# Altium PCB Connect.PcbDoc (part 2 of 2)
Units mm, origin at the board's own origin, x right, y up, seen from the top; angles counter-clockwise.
Board outline 480 x 50 mm, 2 copper layers (Top Layer, Bottom Layer); 349 components, 200 nets, 1147 pads, 734 vias.
Unrouted connection lines stored in the file: 1.
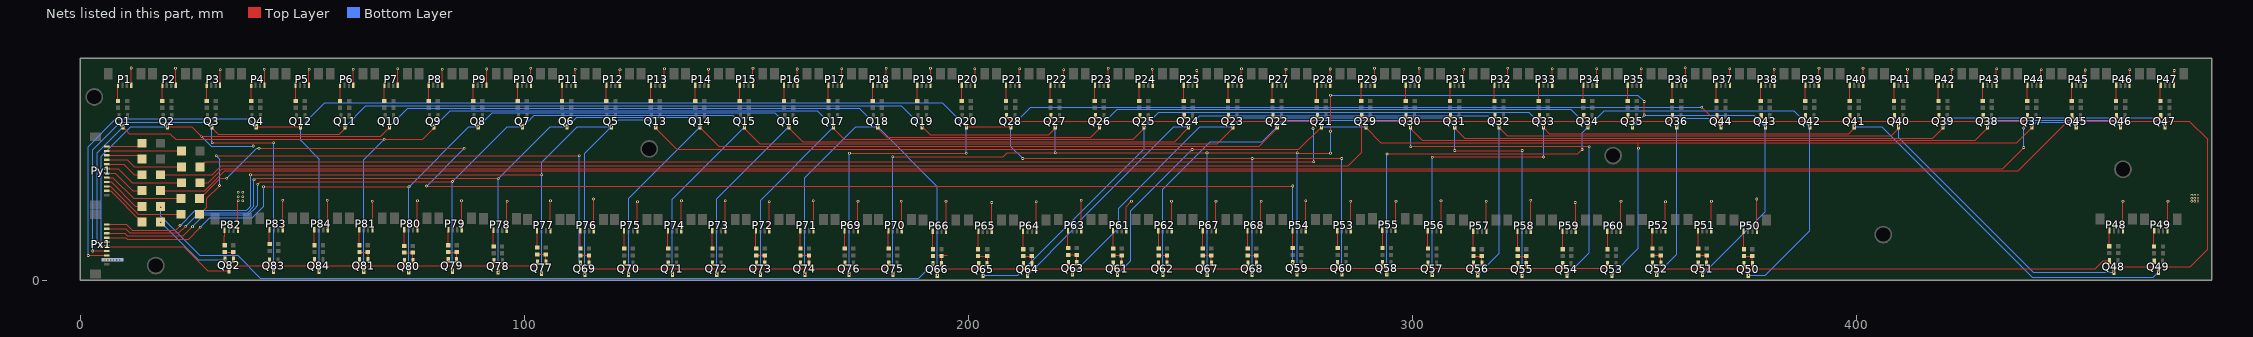
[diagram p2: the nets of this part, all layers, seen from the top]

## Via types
v1: diameter 1.27, hole 0.711, Top Layer to Bottom Layer, tented both sides, 396 vias
v2: diameter 0.6, hole 0.3, Top Layer to Bottom Layer, 231 vias
v3: diameter 0.5, hole 0.3, Top Layer to Bottom Layer, 107 vias

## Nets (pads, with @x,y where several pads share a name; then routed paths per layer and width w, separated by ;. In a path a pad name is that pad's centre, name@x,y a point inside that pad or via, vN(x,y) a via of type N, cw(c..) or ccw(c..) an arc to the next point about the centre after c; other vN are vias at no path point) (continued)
NetD4_1: D4.1 Q21.2 Q22.2 Q23.2 Q24.2 Q25.2 Q26.2 Q27.2 Q28.2 | length 339.4
  Top Layer w0.254: D4.1@26.992,25.527 28.135,26.67 v2(277.749,26.67) ; Q28.2@208.621,37.064 208.621,36.743 209.55,35.814 218.567,35.814 ; Q27.2@218.617,37.064 218.617,35.864 218.567,35.814 ; Q26.2@228.613,37.064 228.613,35.827 228.6,35.814 ; Q25.2@238.609,37.064 238.609,35.838 238.633,35.814 ; Q24.2@248.605,37.064 248.605,35.875 248.666,35.814 ; Q23.2@258.601,37.064 258.601,35.843 258.572,35.814 ; Q22.2@268.597,37.064 268.597,35.822 268.605,35.814 ; v2(277.622,34.163) 277.622,35.814 ; Q21.2@278.593,37.064 278.593,36.785 277.622,35.814 ; 218.567,35.814 228.6,35.814 ; 228.6,35.814 238.633,35.814 ; 238.633,35.814 248.666,35.814 ; 248.666,35.814 258.572,35.814 ; 258.572,35.814 268.605,35.814 ; 268.605,35.814 277.622,35.814
  Bottom Layer w0.254: v2(277.622,34.163) 277.749,34.036 v2(277.749,26.67)
NetD5_1: D5.1 Q29.2 Q30.2 Q31.2 Q32.2 Q33.2 Q34.2 Q35.2 Q36.2 | length 359.5
  Top Layer w0.254: D5.1@18.102,23.749 29.718,23.749 31.75,25.781 285.496,25.781 288.589,28.874 Q29.2@288.589,36.785 ; Q29.2@288.589,37.064 Q29.2@288.589,36.785 ; Q30.2@298.585,37.064 298.585,35.822 298.577,35.814 ; Q31.2@308.581,37.064 308.581,35.843 308.61,35.814 ; Q32.2@318.577,37.064 318.577,35.875 318.516,35.814 ; Q33.2@328.573,37.064 328.573,35.838 328.549,35.814 ; Q34.2@338.569,37.064 338.569,35.814 ; Q35.2@348.565,37.064 348.565,35.891 348.488,35.814 ; Q36.2@358.56,37.064 358.56,36.742 357.632,35.814 348.488,35.814 ; Q29.2@288.589,36.785 289.56,35.814 298.577,35.814 ; 298.577,35.814 308.61,35.814 ; 308.61,35.814 318.516,35.814 ; 318.516,35.814 328.549,35.814 ; 328.549,35.814 338.569,35.814 ; 338.569,35.814 348.488,35.814
NetD6_1: D6.1 Q37.2 Q38.2 Q39.2 Q40.2 Q41.2 Q42.2 Q43.2 Q44.2 | length 498.8
  Top Layer w0.254: D6.1@26.992,21.971 28.829,21.971 32.004,25.146 432.943,25.146 437.642,29.845 v2(437.642,29.909) ; Q44.2@368.556,37.064 368.556,36.828 369.57,35.814 378.587,35.814 ; Q43.2@378.552,37.064 378.552,35.849 378.587,35.814 ; Q42.2@388.548,37.064 388.548,35.886 388.62,35.814 ; Q41.2@398.544,37.064 398.544,35.832 398.526,35.814 ; Q40.2@408.54,37.064 408.54,35.833 408.559,35.814 ; Q39.2@418.536,37.064 418.536,35.885 418.465,35.814 ; Q38.2@428.532,37.064 428.532,35.848 428.498,35.814 ; v2(437.642,34.29) 437.642,35.814 ; Q37.2@438.528,37.064 438.528,36.7 437.642,35.814 ; 378.587,35.814 388.62,35.814 ; 388.62,35.814 398.526,35.814 ; 398.526,35.814 408.559,35.814 ; 408.559,35.814 418.465,35.814 ; 418.465,35.814 428.498,35.814 ; 428.498,35.814 437.642,35.814
  Bottom Layer w0.254: v2(437.642,29.909) v2(437.642,34.29)
NetD7_1: D7.1 Q45.2 Q46.2 Q47.2 Q48.2 Q49.2 Q50.2 Q51.2 Q52.2 | length 629.8
  Top Layer w0.254: D7.1@18.102,20.193 28.067,20.193 32.512,24.638 436.419,24.638 Q45.2@448.524,36.743 ; Q52.2@354.063,3.81 354.063,3.442 354.965,2.54 364.363,2.54 ; Q51.2@364.36,3.81 364.36,2.543 364.363,2.54 ; Q50.2@374.664,3.683 374.664,2.554 374.65,2.54 ; Q45.2@448.524,37.064 Q45.2@448.524,36.743 ; Q46.2@458.52,37.064 458.52,35.864 458.47,35.814 ; Q49.2@467.045,4.298 467.045,3.114 466.979,3.048 ; Q47.2@468.516,37.064 Q47.2@468.516,36.843 ; 364.363,2.54 374.65,2.54 ; 374.65,2.54 453.771,2.54 455.572,4.341 Q48.2@457.006,4.341 457.006,4.004 457.962,3.048 466.979,3.048 ; Q45.2@448.524,36.743 449.453,35.814 458.47,35.814 ; 458.47,35.814 467.487,35.814 Q47.2@468.516,36.843 ; 466.979,3.048 475.107,3.048 479.044,6.985 479.044,31.75 474.98,35.814 469.519,35.814 468.516,36.817 Q47.2@468.516,36.843
NetD8_1: D8.1 Q53.2 Q54.2 Q55.2 Q56.2 Q57.2 Q58.2 Q59.2 Q60.2 | length 367.8
  Top Layer w0.254: D8.1@26.865,18.415 27.712,19.262 27.855,19.262 31.579,22.987 v2(33.02,22.987) ; v2(40.259,29.718) v2(86.487,29.718) ; v2(77.978,21.209) v2(273.05,21.209) ; v2(273.057,3.937) 273.057,3.676 274.056,2.677 283.21,2.677 ; Q60.2@283.167,3.937 283.167,2.72 283.21,2.677 ; Q58.2@293.276,3.937 293.276,2.771 293.37,2.677 ; Q57.2@303.513,3.81 303.513,2.694 303.53,2.677 ; Q56.2@313.756,3.79 313.756,2.738 313.817,2.677 ; Q55.2@323.733,3.683 323.733,2.687 323.723,2.677 ; Q54.2@333.843,3.683 333.843,2.717 333.883,2.677 ; Q53.2@343.953,3.683 343.953,3.339 343.291,2.677 333.883,2.677 ; 283.21,2.677 293.37,2.677 ; 293.37,2.677 303.53,2.677 ; 303.53,2.677 313.817,2.677 ; 313.817,2.677 323.723,2.677 ; 323.723,2.677 333.883,2.677
  Bottom Layer w0.254: v2(33.02,22.987) 39.751,29.718 v2(40.259,29.718) ; v2(77.978,21.209) v2(86.487,29.718) ; v2(273.05,21.209) 273.057,21.202 v2(273.057,3.937)
NetD9_1: D9.1 Q61.2 Q62.2 Q63.2 Q64.2 Q65.2 Q66.2 Q67.2 Q68.2 | length 263.2
  Top Layer w0.254: v2(18.102,16.442) D9.1@18.102,16.637 ; v2(192.024,3.683) Q66.2@192.05,3.683 192.05,3.403 192.913,2.54 202.311,2.54 ; Q65.2@202.333,3.683 202.333,2.562 202.311,2.54 ; Q64.2@212.397,3.683 212.397,2.614 212.471,2.54 ; Q63.2@222.507,3.937 222.507,2.543 222.504,2.54 ; Q61.2@232.617,3.81 232.617,2.587 232.664,2.54 ; Q62.2@242.854,3.81 242.854,2.637 242.951,2.54 ; Q67.2@252.837,3.81 252.837,2.56 252.857,2.54 ; Q68.2@262.947,3.81 262.763,3.626 262.763,3.302 262.001,2.54 252.857,2.54 ; 202.311,2.54 212.471,2.54 ; 212.471,2.54 222.504,2.54 ; 222.504,2.54 232.664,2.54 ; 232.664,2.54 242.951,2.54 ; 242.951,2.54 252.857,2.54
  Bottom Layer w0.254: v2(18.102,16.442) 18.102,14.41 26.924,5.588 35.433,5.588 40.576,0.445 188.785,0.445 v2(192.024,3.683)
NetD10_1: D10.1 Q69.2 Q70.2 Q71.2 Q72.2 Q73.2 Q74.2 Q75.2 Q76.2 | length 200
  Top Layer w0.254: D10.1@26.865,14.859 28.448,16.442 28.448,18.415 v2(31.369,21.336) ; v2(30.607,28.067) v2(112.395,28.067) ; v2(112.695,3.81) 112.695,3.637 113.792,2.54 122.555,2.54 ; Q70.2@122.551,3.81 122.555,3.806 122.555,2.54 ; Q71.2@132.407,3.81 132.407,2.613 132.334,2.54 ; Q72.2@142.39,3.81 142.39,2.563 142.367,2.54 ; Q73.2@152.246,3.81 152.246,2.567 152.273,2.54 ; Q74.2@162.229,3.81 162.306,3.733 162.306,2.54 ; Q76.2@172.212,3.81 172.212,2.54 ; Q75.2@182.068,3.81 181.864,3.606 181.864,3.302 181.102,2.54 172.212,2.54 ; 122.555,2.54 132.334,2.54 ; 132.334,2.54 142.367,2.54 ; 142.367,2.54 152.273,2.54 ; 152.273,2.54 162.306,2.54 ; 162.306,2.54 172.212,2.54
  Bottom Layer w0.254: v2(30.607,28.067) 31.369,27.305 v2(31.369,21.336) ; v2(112.395,28.067) 112.395,4.11 v2(112.695,3.81)
NetD11_1: D11.1 Q77.2 Q78.2 Q79.2 Q80.2 Q81.2 Q82.2 Q83.2 Q84.2 | length 96.8
  Top Layer w0.254: Q82.2@32.578,4.379 33.655,3.302 42.545,3.302 ; Q83.2@42.611,4.532 42.611,3.368 42.545,3.302 ; Q84.2@52.798,4.572 52.798,3.336 52.832,3.302 ; Q81.2@62.908,4.572 62.908,3.386 62.992,3.302 ; Q80.2@73.018,4.445 73.018,3.309 73.025,3.302 ; Q79.2@82.873,4.572 82.873,3.371 82.804,3.302 ; Q78.2@93.157,4.405 93.157,3.302 ; Q77.2@102.966,4.064 102.966,3.779 102.489,3.302 93.157,3.302 ; 42.545,3.302 52.832,3.302 ; 52.832,3.302 62.992,3.302 ; 62.992,3.302 73.025,3.302 ; 73.025,3.302 82.804,3.302 ; 82.804,3.302 93.157,3.302
  Bottom Layer w0.254: v2(18.102,13.081) 26.611,4.572 v2(32.639,4.572)
NetP1_4: P1.4 R85.2 | length 3.5
  Top Layer w0.254: P1.4@8.5,43.925 8.5,40.403 R85.2@8.509,40.394
NetP2_4: P2.4 R86.2 | length 3.5
  Top Layer w0.254: P2.4@18.5,43.925 18.5,40.402 R86.2@18.508,40.394
NetP3_4: P3.4 R87.2 | length 3.5
  Top Layer w0.254: P3.4@28.5,43.925 28.5,40.4 R87.2@28.506,40.394
NetP4_4: P4.4 R88.2 | length 3.5
  Top Layer w0.254: P4.4@38.5,43.925 38.5,40.399 R88.2@38.505,40.394
NetP5_4: P5.4 R89.2 | length 3.5
  Top Layer w0.254: P5.4@48.5,43.925 48.503,43.922 R89.2@48.503,40.394
NetP6_4: P6.4 R90.2 | length 3.5
  Top Layer w0.254: P6.4@58.5,43.925 58.502,43.923 R90.2@58.502,40.394
NetP7_4: P7.4 R91.2 | length 3.5
  Top Layer w0.254: R91.2@68.501,40.394 P7.4@68.501,43.924
NetP8_4: P8.4 R92.2 | length 3.5
  Top Layer w0.254: R92.2@78.499,40.394 P8.4@78.499,43.924
NetP9_4: P9.4 R93.2 | length 3.5
  Top Layer w0.254: R93.2@88.498,40.394 88.498,43.923 P9.4@88.5,43.925
NetP10_4: P10.4 R94.2 | length 3.5
  Top Layer w0.254: R94.2@98.496,40.394 98.496,43.921 P10.4@98.5,43.925
NetP11_4: P11.4 R95.2 | length 3.5
  Top Layer w0.254: R95.2@108.495,40.394 108.495,43.92 P11.4@108.5,43.925
NetP12_4: P12.4 R96.2 | length 3.5
  Top Layer w0.254: R96.2@118.494,40.394 118.494,43.919 P12.4@118.5,43.925
NetP13_4: P13.4 R97.2 | length 3.5
  Top Layer w0.254: R97.2@128.492,40.394 128.492,43.917 P13.4@128.5,43.925
NetP14_4: P14.4 R98.2 | length 3.5
  Top Layer w0.254: R98.2@138.491,40.394 138.491,43.916 P14.4@138.5,43.925
NetP15_4: P15.4 R99.2 | length 3.5
  Top Layer w0.254: R99.2@148.489,40.394 148.489,43.914 P15.4@148.5,43.925
NetP16_4: P16.4 R100.2 | length 3.5
  Top Layer w0.254: R100.2@158.488,40.394 158.488,43.913 P16.4@158.5,43.925
NetP17_4: P17.4 R101.2 | length 3.5
  Top Layer w0.254: R101.2@168.487,40.394 168.487,43.912 P17.4@168.5,43.925
NetP18_4: P18.4 R102.2 | length 3.5
  Top Layer w0.254: R102.2@178.485,40.394 178.485,43.91 P18.4@178.5,43.925
NetP19_4: P19.4 R103.2 | length 3.5
  Top Layer w0.254: R103.2@188.484,40.394 188.484,43.909 P19.4@188.5,43.925
NetP20_4: P20.4 R104.2 | length 3.5
  Top Layer w0.254: R104.2@198.482,40.394 198.482,43.907 P20.4@198.5,43.925
NetP21_4: P21.4 R105.2 | length 3.5
  Top Layer w0.254: R105.2@208.481,40.394 208.481,43.906 P21.4@208.5,43.925
NetP22_4: P22.4 R106.2 | length 3.5
  Top Layer w0.254: R106.2@218.48,40.394 218.48,43.905 P22.4@218.5,43.925
NetP23_4: P23.4 R107.2 | length 3.5
  Top Layer w0.254: R107.2@228.478,40.394 228.478,43.903 P23.4@228.5,43.925
NetP24_4: P24.4 R108.2 | length 3.5
  Top Layer w0.254: R108.2@238.477,40.394 238.477,43.902 P24.4@238.5,43.925
NetP25_4: P25.4 R109.2 | length 3.5
  Top Layer w0.254: R109.2@248.475,40.394 248.475,43.901 P25.4@248.5,43.925
NetP26_4: P26.4 R110.2 | length 3.5
  Top Layer w0.254: R110.2@258.474,40.394 258.474,43.899 P26.4@258.5,43.925
NetP27_4: P27.4 R111.2 | length 3.5
  Top Layer w0.254: R111.2@268.473,40.394 268.473,43.898 P27.4@268.5,43.925
NetP28_4: P28.4 R112.2 | length 3.5
  Top Layer w0.254: R112.2@278.471,40.394 278.471,43.896 P28.4@278.5,43.925
NetP29_4: P29.4 R113.2 | length 3.5
  Top Layer w0.254: R113.2@288.47,40.394 288.47,43.895 P29.4@288.5,43.925
NetP30_4: P30.4 R114.2 | length 3.5
  Top Layer w0.254: R114.2@298.468,40.394 298.468,43.894 P30.4@298.5,43.925
NetP31_4: P31.4 R115.2 | length 3.5
  Top Layer w0.254: R115.2@308.467,40.394 308.467,43.892 P31.4@308.5,43.925
NetP32_4: P32.4 R116.2 | length 3.5
  Top Layer w0.254: R116.2@318.466,40.394 318.466,43.891 P32.4@318.5,43.925
NetP33_4: P33.4 R117.2 | length 3.5
  Top Layer w0.254: R117.2@328.464,40.394 328.464,43.889 P33.4@328.5,43.925
NetP34_4: P34.4 R118.2 | length 3.5
  Top Layer w0.254: R118.2@338.463,40.394 338.463,43.888 P34.4@338.5,43.925
NetP35_4: P35.4 R119.2 | length 3.5
  Top Layer w0.254: R119.2@348.462,40.394 348.462,43.887 P35.4@348.5,43.925
NetP36_4: P36.4 R120.2 | length 3.5
  Top Layer w0.254: R120.2@358.46,40.394 358.46,43.885 P36.4@358.5,43.925
NetP37_4: P37.4 R121.2 | length 3.5
  Top Layer w0.254: R121.2@368.459,40.394 368.459,43.884 P37.4@368.5,43.925
NetP38_4: P38.4 R122.2 | length 3.5
  Top Layer w0.254: R122.2@378.457,40.394 378.457,43.882 P38.4@378.5,43.925
NetP39_4: P39.4 R123.2 | length 3.5
  Top Layer w0.254: R123.2@388.456,40.394 388.456,43.881 P39.4@388.5,43.925
NetP40_4: P40.4 R124.2 | length 3.5
  Top Layer w0.254: R124.2@398.455,40.394 398.455,43.88 P40.4@398.5,43.925
NetP41_4: P41.4 R125.2 | length 3.6
  Top Layer w0.254: R125.2@408.453,40.394 408.453,43.878 P41.4@408.5,43.925
NetP42_4: P42.4 R126.2 | length 3.6
  Top Layer w0.254: R126.2@418.452,40.394 418.452,43.877 P42.4@418.5,43.925
NetP43_4: P43.4 R127.2 | length 3.6
  Top Layer w0.254: R127.2@428.45,40.394 428.45,43.875 P43.4@428.5,43.925
NetP44_4: P44.4 R128.2 | length 3.6
  Top Layer w0.254: R128.2@438.449,40.394 438.449,43.874 P44.4@438.5,43.925
NetP45_4: P45.4 R129.2 | length 3.6
  Top Layer w0.254: R129.2@448.448,40.394 448.448,43.873 P45.4@448.5,43.925
NetP46_4: P46.4 R130.2 | length 3.6
  Top Layer w0.254: R130.2@458.446,40.394 458.446,43.871 P46.4@458.5,43.925
NetP47_4: P47.4 R131.2 | length 3.6
  Top Layer w0.254: R131.2@468.445,40.394 468.445,43.87 P47.4@468.5,43.925
NetP48_4: P48.4 R132.2 | length 3.6
  Top Layer w0.254: R132.2@456.937,7.671 456.937,11.145 P48.4@456.994,11.202
NetP49_4: P49.4 R133.2 | length 3.6
  Top Layer w0.254: R133.2@466.979,7.628 466.979,11.101 P49.4@467.037,11.159
NetP50_4: P50.4 R134.2 | length 4
  Top Layer w0.254: P50.4@374.581,11.014 374.65,10.945 R134.2@374.65,6.993
NetP51_4: P51.4 R135.2 | length 4
  Top Layer w0.254: P51.4@364.277,11.141 364.345,11.073 R135.2@364.345,7.12
NetP52_4: P52.4 R136.2 | length 4
  Top Layer w0.254: P52.4@353.981,11.141 354.048,11.073 R136.2@354.048,7.12
NetP53_4: P53.4 R137.2 | length 3.9
  Top Layer w0.254: P53.4@283.086,11.141 283.149,11.078 R137.2@283.149,7.247
NetP54_4: P54.4 R138.2 | length 3.9
  Top Layer w0.254: P54.4@272.976,11.141 273.038,11.079 R138.2@273.038,7.247
NetP55_4: P55.4 R139.2 | length 4
  Top Layer w0.254: P55.4@293.196,11.268 293.259,11.205 R139.2@293.259,7.247
NetP56_4: P56.4 R140.2 | length 4
  Top Layer w0.254: P56.4@303.432,11.141 303.496,11.077 R140.2@303.496,7.12
NetP57_4: P57.4 R141.2 | length 4
  Top Layer w0.254: P57.4@313.669,11.014 313.734,10.949 R141.2@313.734,6.993
NetP58_4: P58.4 R142.2 | length 4
  Top Layer w0.254: P58.4@323.652,11.014 323.717,10.949 R142.2@323.717,6.993
NetP59_4: P59.4 R143.2 | length 4
  Top Layer w0.254: P59.4@333.761,11.014 333.827,10.948 R143.2@333.827,6.993
NetP60_4: P60.4 R144.2 | length 4
  Top Layer w0.254: P60.4@343.871,11.014 343.938,10.947 R144.2@343.938,6.993
NetP61_4: P61.4 R145.2 | length 4
  Top Layer w0.254: P61.4@232.537,11.141 232.597,11.082 R145.2@232.597,7.12
NetP62_4: P62.4 R146.2 | length 4
  Top Layer w0.254: P62.4@242.774,11.141 242.834,11.081 R146.2@242.834,7.12
NetP63_4: P63.4 R147.2 | length 4
  Top Layer w0.254: P63.4@222.428,11.141 222.428,7.247 R147.2@222.486,7.247
NetP64_4: P64.4 R148.2 | length 4.1
  Top Layer w0.254: P64.4@212.318,11.014 212.318,6.993 R148.2@212.376,6.993
NetP65_4: P65.4 R149.2 | length 4.3
  Top Layer w0.254: R149.2@202.254,6.731 P65.4@202.254,11.014
NetP66_4: P66.4 R150.2 | length 4.1
  Top Layer w0.254: P66.4@191.948,11.014 191.948,6.993 R150.2@192.028,6.993
NetP67_4: P67.4 R151.2 | length 4
  Top Layer w0.254: P67.4@252.757,11.141 252.817,11.08 R151.2@252.817,7.12
NetP68_4: P68.4 R152.2 | length 4
  Top Layer w0.254: P68.4@262.866,11.141 262.928,11.08 R152.2@262.928,7.12
NetP69_4: P69.4 R153.2 | length 4.1
  Top Layer w0.254: P69.4@172.11,11.141 172.11,7.12 R153.2@172.189,7.12
NetP70_4: P70.4 R154.2 | length 4.1
  Top Layer w0.254: P70.4@181.966,11.141 181.966,7.12 R154.2@182.045,7.12
NetP71_4: P71.4 R155.2 | length 4.1
  Top Layer w0.254: P71.4@162.128,11.141 162.128,7.12 R155.2@162.205,7.12
NetP72_4: P72.4 R156.2 | length 4.3
  Top Layer w0.254: P72.4@152.146,11.303 152.146,7.12 R156.2@152.222,7.12
NetP73_4: P73.4 R157.2 | length 4.1
  Top Layer w0.254: P73.4@142.291,11.141 142.291,7.12 R157.2@142.365,7.12
NetP74_4: P74.4 R158.2 | length 4.1
  Top Layer w0.254: P74.4@132.309,11.141 132.309,7.12 R158.2@132.382,7.12
NetP75_4: P75.4 R159.2 | length 4.1
  Top Layer w0.254: P75.4@122.453,11.141 122.453,7.12 R159.2@122.526,7.12
NetP76_4: P76.4 R160.2 | length 4.1
  Top Layer w0.254: P76.4@112.598,11.141 112.598,7.12 R160.2@112.669,7.12
NetP77_4: P77.4 R161.2 | length 4.1
  Top Layer w0.254: R161.2@102.87,7.12 R161.2@102.87,7.374 ; P77.4@102.87,11.176 R161.2@102.87,7.374 ; R161.2@102.94,7.374 R161.2@102.87,7.374
NetP78_4: P78.4 R162.2 | length 4.1
  Top Layer w0.254: R162.2@93.015,7.247 R162.2@93.015,7.628 ; P78.4@93.015,11.268 R162.2@93.015,7.628 ; R162.2@93.084,7.628 R162.2@93.015,7.628
NetP79_4: P79.4 R163.2 | length 3.9
  Top Layer w0.254: R163.2@82.797,7.882 R163.2@82.846,7.882 ; R163.2@82.924,7.501 P79.4@82.924,11.395
NetP80_4: P80.4 R164.2 | length 3.7
  Top Layer w0.254: P80.4@72.942,11.395 72.942,7.755 R164.2@72.99,7.755
NetP81_4: P81.4 R165.2 | length 3.4
  Top Layer w0.254: P81.4@62.814,11.176 62.814,7.882 R165.2@62.88,7.882
NetP82_4: P82.4 R166.2 | length 3.5
  Top Layer w0.254: P82.4@32.503,11.268 32.503,9.957 32.487,9.94 32.487,7.882 R166.2@32.549,7.882
NetP83_4: P83.4 R167.2 | length 3.1
  Top Layer w0.254: P83.4@42.596,11.176 42.596,8.136 R167.2@42.659,8.136
NetP84_4: P84.4 R168.2 | length 3.5
  Top Layer w0.254: R168.2@52.722,7.882 P84.4@52.722,11.395
P00: Px1.1 Q5.3 Q13.3 Q21.3 Q29.3 Q37.3 Q45.3 Q53.3 Q61.3 Q69.3 Q77.3 | length 595.2
  Top Layer w0.254: Px1.1@6.004,12.587 10.4,12.587 11.684,11.303 21.463,11.303 v2(22.479,12.319) ; v2(38.354,23.749) v2(103.916,23.749) ; v2(103.916,1.554) Q77.3@103.916,1.564 ; Q69.3@113.391,1.564 Q69.3@113.645,1.31 v2(113.645,1.29) ; v2(129.603,34.564) 129.603,34.227 134.447,29.383 134.528,29.464 v2(250.444,29.464) 274.443,29.464 v2(279.543,34.564) ; v2(289.56,34.544) 289.56,34.29 292.862,30.988 350.774,30.988 ; v2(350.901,29.718) 350.901,30.861 350.774,30.988 ; v2(439.478,34.564) 439.478,34.348 436.118,30.988 350.774,30.988
  Bottom Layer w0.254: v2(22.479,12.319) 25.908,15.748 37.465,15.748 38.354,16.637 v2(38.354,23.749) ; v2(103.916,1.554) v2(103.916,23.749) 103.916,26.573 111.887,34.544 v2(119.634,34.544) ; v2(113.645,1.29) 113.645,28.555 v2(119.634,34.544) ; v2(129.603,34.564) 127.973,36.195 121.285,36.195 v2(119.634,34.544) ; v2(233.567,1.31) 236.601,4.344 236.601,15.621 v2(250.444,29.464) ; v2(279.543,34.564) 289.54,34.564 v2(289.56,34.544) ; v2(344.903,1.183) 350.901,7.181 v2(350.901,29.718) ; v2(439.478,34.564) 440.474,35.56 448.437,35.56 v2(449.453,34.544)
P01: Px1.2 Q6.3 Q14.3 Q22.3 Q30.3 Q38.3 Q46.3 Q54.3 Q62.3 Q70.3 Q78.3 | length 665.6
  Top Layer w0.254: Px1.2@6.004,11.587 10.257,11.587 11.176,10.668 22.225,10.668 v2(23.749,12.192) ; v2(39.116,22.606) 39.497,22.987 93.98,22.987 v2(94.107,22.86) ; v2(94.107,1.778) Q78.3@94.107,1.905 ; v2(109.612,34.555) Q6.3@109.612,34.564 ; v2(123.484,1.31) Q70.3@123.501,1.31 ; Q14.3@139.599,34.391 143.764,30.226 265.557,30.226 Q22.3@269.547,34.216 ; v2(243.804,1.306) Q62.3@243.804,1.31 ; Q30.3@299.535,34.564 v2(299.573,34.564) ; v2(299.593,30.099) 299.639,30.145 339.806,30.145 v2(339.852,30.099) ; Q30.3@299.593,34.544 299.593,34.163 302.26,31.496 426.72,31.496 429.482,34.258 v2(429.482,34.564)
  Bottom Layer w0.254: v2(23.749,12.192) 26.797,15.24 37.675,15.24 39.116,16.681 v2(39.116,22.606) ; v2(94.107,1.778) v2(94.107,22.86) 105.802,34.555 v2(109.612,34.555) 111.76,36.703 137.414,36.703 v2(139.573,34.544) 123.484,18.455 v2(123.484,1.31) ; v2(243.804,1.306) 243.804,20.538 254.508,31.242 266.225,31.242 v2(269.547,34.564) 269.547,34.597 271.018,36.068 298.069,36.068 v2(299.573,34.564) 299.593,34.544 v2(299.593,30.099) ; v2(334.793,1.183) 339.852,6.242 v2(339.852,30.099) ; v2(429.482,34.564) 430.986,36.068 457.962,36.068 v2(459.486,34.544)
P02: Px1.3 Q7.3 Q15.3 Q23.3 Q31.3 Q39.3 Q47.3 Q55.3 Q63.3 Q71.3 Q79.3 | length 649.8
  Top Layer w0.254: Px1.3@6.004,10.587 9.987,10.587 10.541,10.033 23.241,10.033 v2(25.273,12.065) ; v2(40.005,21.59) 40.559,22.144 83.739,22.144 v2(83.824,22.229) ; Q79.3@83.824,1.782 v2(83.824,2.072) ; Q15.3@149.595,34.544 149.595,34.174 153.035,30.734 256.032,30.734 259.551,34.253 v2(259.551,34.564) ; v2(223.417,1.397) Q63.3@223.457,1.437 ; v2(309.499,29.21) v2(324.739,29.21) ; v2(309.531,34.564) 309.531,34.258 311.785,32.004 417.195,32.004 419.486,34.295 v2(419.486,34.564)
  Bottom Layer w0.254: v2(25.273,12.065) 27.94,14.732 37.886,14.732 39.624,16.47 39.624,16.51 40.005,16.891 v2(40.005,21.59) ; v2(83.824,2.072) v2(83.824,22.229) 96.159,34.564 v2(99.616,34.564) 102.263,37.211 146.939,37.211 v2(149.606,34.544) 133.357,18.295 v2(133.357,1.31) ; v2(223.417,1.397) 233.811,11.791 233.811,16.26 252.115,34.564 v2(259.551,34.564) 261.563,36.576 307.455,36.576 309.499,34.532 v2(309.499,29.21) ; v2(324.739,1.143) v2(324.739,29.21) ; v2(419.486,34.564) 421.498,36.576 467.487,36.576 v2(469.519,34.544)
P03: Px1.4 Q8.3 Q16.3 Q24.3 Q32.3 Q40.3 Q48.3 Q56.3 Q64.3 Q72.3 Q80.3 | length 634.1
  Top Layer w0.254: Px1.4@6.004,9.587 10.225,9.587 10.541,9.271 24.384,9.271 v2(27.051,11.938) ; v2(41.275,21.082) v2(74.041,21.082) ; Q72.3@143.34,1.31 v2(143.34,1.354) ; v2(159.591,34.564) 159.591,34.338 162.687,31.242 246.507,31.242 Q24.3@249.555,34.29 ; Q32.3@319.532,34.559 319.532,34.29 321.31,32.512 407.797,32.512 Q40.3@409.49,34.205 ; Q40.3@409.49,34.564 v2(409.51,34.544)
  Bottom Layer w0.254: v2(27.051,11.938) 29.21,14.097 38.735,14.097 41.275,16.637 v2(41.275,21.082) ; v2(73.968,1.945) 73.968,21.009 v2(74.041,21.082) 87.503,34.544 v2(89.662,34.544) 92.837,37.719 156.436,37.719 v2(159.591,34.564) 143.34,18.313 v2(143.34,1.354) ; v2(213.347,1.183) 223.778,11.614 223.778,12.072 246.25,34.544 v2(249.555,34.544) 252.095,37.084 317.007,37.084 v2(319.527,34.564) 319.527,6.121 319.532,6.116 v2(314.706,1.29) ; v2(409.51,34.544) 409.51,32.069 439.801,1.778 v2(457.962,1.778)
P04: Px1.5 Q1.3 Q9.3 Q17.3 Q25.3 Q33.3 Q41.3 Q49.3 Q57.3 Q65.3 Q73.3 Q81.3 | length 698.1
  Top Layer w0.254: v2(3.81,8.636) 5.955,8.636 Px1.5@6.004,8.587 ; v2(9.652,34.564) 9.652,34.417 11.049,33.02 20.193,33.02 21.463,31.75 v2(68.453,31.75) 77.089,31.75 79.375,34.036 Q9.3@79.629,34.036 ; v2(63.858,2.055) Q81.3@63.858,2.072 ; Q17.3@169.587,34.248 172.085,31.75 237.109,31.75 239.559,34.2 v2(239.559,34.564) ; v2(304.461,27.688) 304.461,27.771 v2(329.523,27.771) ; v2(329.523,34.564) 329.523,34.332 330.835,33.02 398.272,33.02 Q41.3@399.494,34.242 ; Q41.3@399.494,34.564 v2(399.514,34.544)
  Bottom Layer w0.254: v2(3.81,8.636) 3.81,28.722 v2(9.652,34.564) ; v2(63.858,2.055) 63.858,27.155 v2(68.453,31.75) ; v2(79.624,34.564) 83.287,38.227 165.989,38.227 v2(169.672,34.544) 153.196,18.068 v2(153.196,1.31) ; v2(203.327,1.143) 211.074,1.143 239.559,29.628 v2(239.559,34.564) 242.841,37.846 326.241,37.846 v2(329.523,34.564) v2(329.523,27.771) ; v2(304.461,27.688) 304.463,27.686 v2(304.463,1.31) ; v2(399.514,34.544) 405.638,34.544 439.547,0.635 466.852,0.635 v2(467.995,1.778)
P05: Px1.6 Q2.3 Q10.3 Q18.3 Q26.3 Q34.3 Q42.3 Q50.3 Q58.3 Q66.3 Q74.3 Q82.3 | length 665.8
  Top Layer w0.254: v2(4.699,7.62) 5.971,7.62 Px1.6@6.004,7.587 23.274,7.587 28.702,2.159 33.508,2.159 Q82.3@33.528,2.179 ; v2(19.648,34.564) 25.126,34.564 v3(27.305,32.385) 67.691,32.385 69.628,34.322 v2(69.628,34.564) ; v2(179.583,34.564) 179.583,34.285 181.61,32.258 227.584,32.258 229.563,34.237 v2(229.563,34.564) ; v2(294.259,28.448) 294.263,28.452 329.805,28.452 329.808,28.448 337.185,28.448 v2(338.201,29.464) ; Q34.3@339.519,34.564 v2(339.539,34.544)
  Bottom Layer w0.254: v2(4.699,7.62) 4.699,27.94 11.323,34.564 v2(19.648,34.564) ; v3(27.305,32.385) 29.464,30.226 v2(38.989,30.226) ; v2(69.628,34.564) 73.799,38.735 175.412,38.735 v2(179.583,34.564) ; v2(163.179,1.31) 163.179,23.098 174.645,34.564 v2(179.583,34.564) ; v2(193.04,1.143) 193.04,21.107 v2(179.583,34.564) ; v2(229.563,34.564) 233.48,38.481 335.602,38.481 v2(339.539,34.544) ; v2(294.259,1.397) v2(294.259,28.448) ; v2(338.201,29.464) 338.201,33.206 v2(339.539,34.544) ; v2(375.666,1.143) 379.476,1.143 389.498,11.165 v2(389.498,34.564) 385.916,38.146 343.141,38.146 v2(339.539,34.544)
P06: Px1.7 Q3.3 Q11.3 Q19.3 Q27.3 Q35.3 Q43.3 Q51.3 Q59.3 Q67.3 Q75.3 Q83.3 | length 643.9
  Top Layer w0.254: v2(2.794,6.604) 5.987,6.604 Px1.7@6.004,6.587 ; v2(29.644,34.564) 29.644,34.364 31.115,32.893 58.293,32.893 59.632,34.232 v2(59.632,34.564) ; v2(29.697,30.988) v2(43.561,30.988) ; v2(183.007,27.813) 207.899,27.813 208.788,28.702 v2(219.583,28.702) v2(253.746,28.702) v2(274.066,28.702) 274.193,28.575 v2(281.559,28.575) ; Q75.3@183.018,1.31 v2(183.018,1.386) ; v2(189.579,34.564) 191.377,32.766 218.059,32.766 219.329,34.036 Q27.3@219.583,34.036 ; v2(219.567,34.56) Q27.3@219.567,34.564 ; v2(281.559,33.528) v2(281.559,41.656) ; v2(352.171,37.211) v2(352.171,40.259) ; Q43.3@379.476,34.036 Q43.3@379.603,34.036
  Bottom Layer w0.254: v2(2.794,6.604) 2.794,29.337 9.017,35.56 28.648,35.56 v2(29.644,34.564) 29.644,31.041 v2(29.697,30.988) ; v2(43.561,2.032) v2(43.561,30.988) ; v2(59.632,34.564) 64.311,39.243 184.9,39.243 v2(189.579,34.564) ; v2(183.007,27.813) 183.018,27.802 v2(183.018,1.386) ; v2(219.567,34.56) 219.567,28.718 v2(219.583,28.702) ; v2(253.746,1.27) v2(253.746,28.702) ; v2(274.007,1.437) v2@274.007,28.643 ; v2@281.432,33.401 v2(281.559,33.528) v2(281.559,28.575) ; v2(281.559,41.656) 350.774,41.656 v2(352.171,40.259) ; v2(349.504,34.544) v2(352.171,37.211) 376.809,37.211 v2(379.476,34.544) 379.476,15.447 376.344,12.315 376.294,12.315 365.339,1.36 v2(365.339,1.31)
P07: Px1.8 Q4.3 Q12.3 Q20.3 Q28.3 Q36.3 Q44.3 Q52.3 Q60.3 Q68.3 Q76.3 Q84.3 | length 681.1
  Top Layer w0.254: v2(1.778,5.588) v2(1.778,5.588) Px1.8@6.004,5.587 ; Q4.3@39.64,34.564 v2(49.636,34.564) ; Q76.3@173.101,0.889 Q76.3@173.228,0.889 ; v2(173.228,28.575) v2(199.517,28.575) ; v2(199.537,34.564) Q20.3@199.575,34.564 Q28.3@209.571,34.564 ; v2(212.217,27.432) v2(263.906,27.432) v2(284.117,27.432) ; v2(354.973,1.27) Q52.3@355.013,1.31 ; Q36.3@359.51,34.063 Q36.3@359.537,34.089 ; v2(365.125,38.989) 365.125,38.945 Q44.3@369.506,34.564
  Bottom Layer w0.254: v2(1.778,5.588) 1.778,30.099 8.001,36.322 37.846,36.322 v2(39.624,34.544) ; v2(53.848,2.032) 53.848,27.305 49.636,31.517 v2(49.636,34.564) 55.077,40.005 194.096,40.005 v2(199.537,34.564) 199.537,28.595 v2(199.517,28.575) ; v2(173.162,1.31) 173.228,1.376 v2(173.228,28.575) ; v2(212.217,27.432) 209.55,30.099 v2(209.55,34.544) 213.995,38.989 v2(365.125,38.989) ; v2(263.897,1.31) 263.897,27.423 v2(263.906,27.432) ; v2(284.117,1.437) v2(284.117,27.432) ; v2(354.973,1.27) 359.537,5.834 v2(359.537,34.544) 361.442,36.449 367.665,36.449 v2(369.57,34.544)
P11: D1.2 Py1.1 | length 8.2
  Top Layer w0.254: Py1.1@6.004,30.138 13.179,30.138 D1.2@13.902,30.861
P12: D2.2 Py1.2 | length 16.8
  Top Layer w0.254: Py1.2@6.004,29.138 22.737,29.138 D2.2@22.792,29.083
P13: D3.2 Py1.3 | length 8.2
  Top Layer w0.254: Py1.3@6.004,28.138 13.069,28.138 D3.2@13.902,27.305
P14: D4.2 Py1.4 | length 17.5
  Top Layer w0.254: Py1.4@6.004,27.138 10.581,27.138 12.192,25.527 D4.2@22.792,25.527
P15: D5.2 Py1.5 | length 8.9
  Top Layer w0.254: Py1.5@6.004,26.138 9.803,26.138 12.192,23.749 D5.2@13.902,23.749
P16: D6.2 Py1.6 | length 18.1
  Top Layer w0.254: Py1.6@6.004,25.138 8.517,25.138 11.684,21.971 D6.2@22.792,21.971
P17: D7.2 Py1.7 | length 9.5
  Top Layer w0.254: Py1.7@6.004,24.138 7.866,24.138 11.811,20.193 D7.2@13.902,20.193
P24: D11.2 Py1.11 | length 10.8
  Top Layer w0.254: Py1.11@6.004,20.138 6.845,20.138 D11.2@13.902,13.081
P25: D10.2 Py1.10 | length 19.3
  Top Layer w0.254: Py1.10@6.004,21.138 6.802,21.138 13.081,14.859 D10.2@22.665,14.859
P26: D9.2 Py1.9 | length 10.2
  Top Layer w0.254: Py1.9@6.004,22.138 6.945,22.138 12.446,16.637 D9.2@13.902,16.637
P27: D8.2 Py1.8 | length 18.6
  Top Layer w0.254: Py1.8@6.004,23.138 7.342,23.138 12.065,18.415 D8.2@22.665,18.415
RECORD: Q50.1 R50.2 R134.1 | length 3.7
  Top Layer w0.254: R134.1@374.65,5.453 R50.2@376.555,5.453 376.555,3.692 Q50.1@376.564,3.683
REPLAY: Q74.1 R74.2 R155.1 | length 3.7
  Top Layer w0.254: R155.1@162.205,5.58 R74.2@164.11,5.58 164.129,5.58 Q74.1@164.129,3.81
RHY1: Q61.1 R61.2 R145.1 | length 3.7
  Top Layer w0.254: R145.1@232.597,5.58 R61.2@234.502,5.58 234.502,3.825 Q61.1@234.517,3.81
RHY2: Q62.1 R62.2 R146.1 | length 3.7
  Top Layer w0.254: R146.1@242.834,5.58 R62.2@244.739,5.58 244.739,3.825 Q62.1@244.754,3.81
RHY3: Q55.1 R55.2 R142.1 | length 3.7
  Top Layer w0.254: R142.1@323.717,5.453 R55.2@325.622,5.453 325.622,3.694 Q55.1@325.633,3.683
RHY4: Q56.1 R56.2 R141.1 | length 3.7
  Top Layer w0.254: R141.1@313.734,5.453 R56.2@315.639,5.453 315.639,3.694 Q56.1@315.65,3.683
RHY5: Q65.1 R65.2 R149.1 | length 3.8
  Top Layer w0.254: R149.1@202.393,5.453 R65.2@204.216,5.453 204.314,5.453 204.314,3.683 Q65.1@204.233,3.683
RHY6: Q66.1 R66.2 R150.1 | length 3.7
  Top Layer w0.254: 193.298,5.58 195.203,5.58 ; R66.2@193.933,5.453 193.95,5.453 Q66.1@193.95,3.683
RHY7: Q67.1 R67.2 R151.1 | length 3.7
  Top Layer w0.254: R151.1@252.817,5.58 R67.2@254.723,5.58 254.723,3.824 Q67.1@254.737,3.81
RHY8: Q68.1 R68.2 R152.1 | length 3.7
  Top Layer w0.254: R152.1@262.928,5.58 R68.2@264.833,5.58 264.833,3.824 Q68.1@264.847,3.81
RHY9: Q63.1 R63.2 R147.1 | length 3.7
  Top Layer w0.254: R147.1@222.486,5.707 R63.2@224.391,5.707 224.407,5.707 Q63.1@224.407,3.937
RHY10: Q64.1 R64.2 R148.1 | length 3.7
  Top Layer w0.254: R148.1@212.376,5.453 R64.2@214.281,5.453 214.297,5.453 Q64.1@214.297,3.683
RHY_EDIT: Q69.1 R69.2 R160.1 | length 3.7
  Top Layer w0.254: R160.1@112.669,5.58 R69.2@114.574,5.58 114.595,5.58 Q69.1@114.595,3.81
SINGLE: Q77.1 R77.2 R161.1 | length 3.7
  Top Layer w0.254: R161.1@102.94,5.834 R77.2@104.845,5.834 104.866,5.834 Q77.1@104.866,4.064
STOP: Q73.1 R73.2 R156.1 | length 3.7
  Top Layer w0.254: R156.1@152.222,5.58 R73.2@154.127,5.58 154.146,5.58 Q73.1@154.146,3.81
TEMPO+: Q79.1 R79.2 R163.1 | length 3.7
  Top Layer w0.254: R163.1@82.846,6.342 R79.2@84.751,6.342 84.774,6.342 Q79.1@84.774,4.572
TEMPO-: Q80.1 R80.2 R164.1 | length 3.7
  Top Layer w0.254: R164.1@72.99,6.215 R80.2@74.895,6.215 74.918,6.215 Q80.1@74.918,4.445
TONE1: Q52.1 R52.2 R136.1 | length 3.7
  Top Layer w0.254: R136.1@354.048,5.58 R52.2@355.953,5.58 355.953,3.82 Q52.1@355.963,3.81
TONE2: Q51.1 R51.2 R135.1 | length 3.7
  Top Layer w0.254: R135.1@364.345,5.58 R51.2@366.251,5.58 366.251,3.819 Q51.1@366.26,3.81
VCC: P1.1 P2.1 P3.1 P4.1 P5.1 P6.1 P7.1 P8.1 P9.1 P10.1 P11.1 P12.1 P13.1 P14.1 P15.1 P16.1 P17.1 P18.1 P19.1 P20.1 P21.1 P22.1 P23.1 P24.1 P25.1 P26.1 P27.1 P28.1 P29.1 P30.1 P31.1 P32.1 P33.1 P34.1 P35.1 P36.1 P37.1 P38.1 P39.1 P40.1 P41.1 P42.1 P43.1 P44.1 P45.1 P46.1 P47.1 P48.1 P49.1 P50.1 P51.1 P52.1 P53.1 P54.1 P55.1 P56.1 P57.1 P58.1 P59.1 P60.1 P61.1 P62.1 P63.1 P64.1 P65.1 P66.1 P67.1 P68.1 P69.1 P70.1 P71.1 P72.1 P73.1 P74.1 P75.1 P76.1 P77.1 P78.1 P79.1 P80.1 P81.1 P82.1 P83.1 P84.1 pad.2 Px1.9 | length 420.7
  Top Layer w0.254: v2(11.487,47.809) 11.5,47.809 P1.1@11.5,43.925 ; v2(21.463,47.752) 21.5,47.715 P2.1@21.5,43.925 ; v2(31.496,47.371) 31.5,47.367 P3.1@31.5,43.925 ; P82.1@35.503,11.268 35.503,17.85 v2(35.56,17.907) ; v2(41.471,47.498) 41.5,47.469 P4.1@41.5,43.925 ; v2(45.593,18.034) 45.613,18.014 P83.1@45.613,11.395 ; P5.1@51.5,43.925 51.5,47.436 v2(51.562,47.498) ; v2(55.626,18.034) 55.722,17.938 P84.1@55.722,11.395 ; v2(61.468,47.498) 61.5,47.466 P6.1@61.5,43.925 ; v2(65.786,17.78) 65.832,17.734 P81.1@65.832,11.395 ; P7.1@71.5,43.925 v2(71.501,47.625) v2(71.501,47.625) ; P80.1@75.942,11.395 75.942,17.903 v2(75.946,17.907) ; P8.1@81.5,43.925 81.5,47.464 v2(81.534,47.498) ; v2(85.852,17.907) 85.924,17.835 P79.1@85.924,11.395 ; P9.1@91.5,43.925 91.5,47.565 v2(91.507,47.565) ; P78.1@96.034,11.268 96.034,17.675 v2(96.139,17.78) ; v2(101.473,47.752) 101.5,47.725 P10.1@101.5,43.925 ; P77.1@105.89,11.141 105.89,17.879 v2(105.918,17.907) ; P11.1@111.5,43.925 111.5,47.492 v2(111.506,47.498) ; v2(115.57,18.288) 115.618,18.24 P76.1@115.618,11.141 ; P12.1@121.5,43.925 121.5,47.332 v2(121.539,47.371) ; P75.1@125.474,11.141 125.474,17.651 v2(125.476,17.653) ; P13.1@131.5,43.925 131.5,47.553 v2(131.572,47.625) ; P74.1@135.33,11.141 135.33,17.832 v2(135.382,17.885) ; v2(141.478,47.498) 141.5,47.476 P14.1@141.5,43.925 ; v2(145.288,17.907) 145.288,11.165 P73.1@145.312,11.141 ; P15.1@151.5,43.925 151.5,47.741 v2(151.511,47.752) ; P72.1@155.168,11.141 v3(155.168,17.679) ; P16.1@161.5,43.925 v2(161.5,47.581) ; v2(165.1,17.907) 165.151,17.856 P71.1@165.151,11.141 ; v2(171.45,47.625) 171.5,47.575 P17.1@171.5,43.925 ; P69.1@175.133,11.141 v2(175.133,17.78) ; v2(181.483,47.752) 181.5,47.735 P18.1@181.5,43.925 ; v2(184.912,17.78) 184.989,17.703 P70.1@184.989,11.141 ; v2(191.484,47.752) 191.5,47.736 P19.1@191.5,43.925 ; v2(194.945,17.78) 194.972,17.753 P66.1@194.972,11.014 ; v2(201.422,47.625) 201.5,47.547 P20.1@201.5,43.925 ; v2(205.232,17.526) 205.232,17.399 205.254,17.377 P65.1@205.254,11.014 ; P21.1@211.5,43.925 211.5,47.543 v2(211.582,47.625) ; v2(215.265,17.653) 215.318,17.6 P64.1@215.318,11.014 ; v2(221.488,47.371) 221.5,47.359 P22.1@221.5,43.925 ; v2(225.425,18.028) 225.428,18.031 P63.1@225.428,11.141 ; P23.1@231.5,43.925 231.5,47.731 v2(231.521,47.752) ; P61.1@235.537,11.141 235.537,16.589 v2(236.728,17.78) ; v2(241.427,47.498) 241.5,47.425 P24.1@241.5,43.925 ; v2(245.745,17.78) 245.774,17.751 P62.1@245.774,11.141 ; v2(251.46,47.244) 251.5,47.204 P25.1@251.5,43.925 ; P67.1@255.757,11.141 255.757,17.759 v2(255.778,17.78) ; v2(261.493,47.625) 261.5,47.618 P26.1@261.5,43.925 ; P68.1@265.866,11.141 265.866,17.708 v2(265.938,17.78) ; P27.1@271.5,43.925 271.5,47.472 v2(271.526,47.498) ; v2(275.971,17.907) 275.976,17.902 P54.1@275.976,11.141 ; P28.1@281.5,43.925 v2(281.5,47.557) ; P53.1@286.086,11.141 286.086,17.735 v2(286.131,17.78) ; v2(291.465,47.752) 291.5,47.717 P29.1@291.5,43.925 ; P55.1@296.195,11.268 296.195,17.684 v2(296.291,17.78) ; v2(301.498,47.752) 301.5,47.75 P30.1@301.5,43.925 ; P56.1@306.432,11.141 v2(306.432,17.888) ; P31.1@311.5,43.925 311.5,47.467 v2(311.531,47.498) ; v2(316.611,17.78) 316.669,17.722 P57.1@316.669,11.014 ; v2(321.437,47.752) 321.5,47.689 P32.1@321.5,43.925 ; v2(326.636,18.026) 326.652,18.026 P58.1@326.652,11.014 ; v2(331.47,47.625) 331.5,47.595 P33.1@331.5,43.925 ; v2(336.677,17.526) 336.761,17.442 P59.1@336.761,11.014 ; P34.1@341.5,43.925 341.5,47.622 v2(341.503,47.625) ; P60.1@346.871,11.014 346.871,17.687 v2(346.964,17.78) ; P35.1@351.5,43.925 351.5,47.589 v2(351.536,47.625) ; P52.1@356.981,11.141 356.981,17.637 v2(356.997,17.653) ; v2(361.442,47.879) 361.5,47.821 P36.1@361.5,43.925 ; P51.1@367.277,11.141 367.344,11.208 v2(367.344,17.78) ; v2(371.475,47.625) 371.5,47.6 P37.1@371.5,43.925 ; v2(377.571,18.288) 377.581,18.278 P50.1@377.581,11.014 ; P38.1@381.5,43.925 381.5,47.49 v2(381.508,47.498) ; P39.1@391.5,43.925 391.5,47.711 v2(391.541,47.752) ; v2(401.447,47.752) 401.5,47.699 P40.1@401.5,43.925 ; v2(411.48,47.498) 411.5,47.478 P41.1@411.5,43.925 ; P42.1@421.5,43.925 421.5,47.485 v2(421.513,47.498) ; P43.1@431.5,43.925 431.5,47.579 v2(431.546,47.625) ; P44.1@441.5,43.925 441.5,47.292 v2(441.579,47.371) ; P45.1@451.5,43.925 v2(451.5,47.356) ; P48.1@459.994,11.202 v2(459.994,17.78) ; P46.1@461.5,43.925 461.5,47.353 v2(461.518,47.371) ; P49.1@470.037,11.032 P49.1@470.037,11.159 470.037,17.663 v2(470.154,17.78) ; P47.1@471.5,43.925 471.5,47.193 v2(471.551,47.244)
  other v3: 5.588,4.572 6.223,4.572 6.858,4.572 7.493,4.572 8.255,4.572 8.89,4.572 475.488,17.78 476.186,17.78 476.885,17.78 36.576,17.907 475.488,18.479 476.186,18.479 476.885,18.479 35.56,18.796 36.576,18.796 475.488,19.177 476.186,19.177 476.885,19.177 35.56,19.812 36.576,19.812
VOL+: Q81.1 R81.2 R165.1 | length 3.7
  Top Layer w0.254: R165.1@62.88,6.342 R81.2@64.785,6.342 64.808,6.342 Q81.1@64.808,4.572
VOL-: Q82.1 R82.2 R166.1 | length 3.6
  Top Layer w0.254: R166.1@32.549,6.342 R82.2@34.454,6.342 34.478,6.342 Q82.1@34.478,4.679
pads on no net: P1.0 P1.3 P2.0 P2.3 P3.0 P3.3 P4.0 P4.3 P5.0 P5.3 P6.0 P6.3 P7.0 P7.3 P8.0 P8.3 P9.0 P9.3 P10.0 P10.3 P11.0 P11.3 P12.0 P12.3 P13.0 P13.3 P14.0 P14.3 P15.0 P15.3 P16.0 P16.3 P17.0 P17.3 P18.0 P18.3 P19.0 P19.3 P20.0 P20.3 P21.0 P21.3 P22.0 P22.3 P23.0 P23.3 P24.0 P24.3 P25.0 P25.3 P26.0 P26.3 P27.0 P27.3 P28.0 P28.3 P29.0 P29.3 P30.0 P30.3 P31.0 P31.3 P32.0 P32.3 P33.0 P33.3 P34.0 P34.3 P35.0 P35.3 P36.0 P36.3 P37.0 P37.3 P38.0 P38.3 P39.0 P39.3 P40.0 P40.3 P41.0 P41.3 P42.0 P42.3 P43.0 P43.3 P44.0 P44.3 P45.0 P45.3 P46.0 P46.3 P47.0 P47.3 P48.0 P48.3 P49.0 P49.3 P50.0 P50.3 P51.0 P51.3 P52.0 P52.3 P53.0 P53.3 P54.0 P54.3 P55.0 P55.3 P56.0 P56.3 P57.0 P57.3 P58.0 P58.3 P59.0 P59.3 P60.0 P60.3 P61.0 P61.3 P62.0 P62.3 P63.0 P63.3 P64.0 P64.3 P65.0 P65.3 P66.0 P66.3 P67.0 P67.3 P68.0 P68.3 P69.0 P69.3 P70.0 P70.3 P71.0 P71.3 P72.0 P72.3 P73.0 P73.3 P74.0 P74.3 P75.0 P75.3 P76.0 P76.3 P77.0 P77.3 P78.0 P78.3 P79.0 P79.3 P80.0 P80.3 P81.0 P81.3 P82.0 P82.3 P83.0 P83.3 P84.0 P84.3 Px1.0 Py1.0 Py1.12

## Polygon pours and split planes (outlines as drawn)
GND on Top Layer "GND_L01_P004" (hatched 90Degree grid 0 track 0.254, remove dead copper, pour order 4): 480,0 480,50 0,50 0,0
GND on Bottom Layer "GND_L02_P006" (hatched 90Degree grid 0 track 0.254, remove dead copper, pour order 6): 480,0 480,50 0,50 0,0

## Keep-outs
Keep-Out Layer:
  the board outline again, w0.127

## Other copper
Top Layer:
  rectangle net VCC: 5.207,4.191 9.271,4.953
  rectangle net VCC: 35.179,17.272 478.155,20.447
Bottom Layer:
  rectangle net VCC: 6.985,4.191 9.906,20.32
  rectangle net VCC: 6.985,17.272 36.83,20.447
  rectangle net VCC: 7.747,45.339 478.282,48.895
  rectangle net VCC: 474.853,17.272 478.282,48.133

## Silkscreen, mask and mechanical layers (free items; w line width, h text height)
Top Overlay:
  text "C4" at 7.112,34.036 h3 r90
  text "C4#" at 17.108,34.036 h3 r90
  text "D4" at 27.104,34.036 h3 r90
  text "D4#" at 37.1,34.036 h3 r90
  text "E4" at 47.096,34.036 h3 r90
  text "F4" at 57.092,34.036 h3 r90
  text "F4#" at 67.088,34.036 h3 r90
  text "G4" at 77.084,34.036 h3 r90
  text "G4#" at 87.08,34.036 h3 r90
  text "A4" at 97.076,34.036 h3 r90
  text "A4#" at 107.072,34.036 h3 r90
  text "B4" at 117.068,34.036 h3 r90
  text "C5" at 127.063,34.036 h3 r90
  text "C5#" at 137.059,34.036 h3 r90
  text "D5" at 147.055,34.036 h3 r90
  text "D5#" at 157.051,34.036 h3 r90
  text "E5" at 167.047,34.036 h3 r90
  text "F5" at 177.043,34.036 h3 r90
  text "F5#" at 187.039,34.036 h3 r90
  text "G5" at 197.035,34.036 h3 r90
  text "G5#" at 207.031,34.036 h3 r90
  text "A5" at 217.027,34.036 h3 r90
  text "A5#" at 227.023,34.036 h3 r90
  text "B5" at 237.019,34.036 h3 r90
  text "C6" at 247.015,34.036 h3 r90
  text "C6#" at 257.011,34.036 h3 r90
  text "D6" at 267.007,34.036 h3 r90
  text "D6#" at 277.003,34.036 h3 r90
  text "E6" at 286.999,34.036 h3 r90
  text "F6" at 296.995,34.036 h3 r90
  text "F6#" at 306.991,34.036 h3 r90
  text "G6" at 316.987,34.036 h3 r90
  text "G6#" at 326.983,34.036 h3 r90
  text "A6" at 336.979,34.036 h3 r90
  text "A6#" at 346.975,34.036 h3 r90
  text "B6" at 356.97,34.036 h3 r90
  text "C7" at 366.966,34.036 h3 r90
  text "C7#" at 376.962,34.036 h3 r90
  text "D7" at 386.958,34.036 h3 r90
  text "D7#" at 396.954,34.036 h3 r90
  text "E7" at 406.95,34.036 h3 r90
  text "F7" at 416.946,34.036 h3 r90
  text "F7#" at 426.942,34.036 h3 r90
  text "G7" at 436.938,34.036 h3 r90
  text "G7#" at 446.934,34.036 h3 r90
  text "A7" at 456.93,34.036 h3 r90
  text "A7#" at 466.926,34.036 h3 r90
  text "B7" at 455.416,1.313 h3 r90
  text "C8" at 465.455,1.143 h3 r90
  text "LEA" at 40.857,0.762 h3 r90
  text "DEM" at 50.979,0.762 h3 r90
  text "VO+" at 61.102,0.762 h3 r90
  text "TE-" at 71.225,0.762 h3 r90
  text "TE+" at 81.22,0.762 h3 r90
  text "VO-" at 30.734,0.635 h3 r90
  text "FIN" at 91.343,0.635 h3 r90
  text "RH0" at 210.783,0.635 h3 r90
  text "DR6" at 291.764,0.635 h3 r90
  text "SIN" at 101.212,0.508 h3 r90
  text "RHY" at 110.953,0.508 h3 r90
  text "DRU" at 120.822,0.508 h3 r90
  text "DR3" at 130.69,0.508 h3 r90
  text "DR4" at 140.686,0.508 h3 r90
  text "STO" at 150.555,0.508 h3 r90
  text "reP" at 160.55,0.508 h3 r90
  text "Fil" at 170.546,0.508 h3 r90
  text "1K1" at 180.415,0.508 h3 r90
  text "RH9" at 220.905,0.508 h3 r90
  text "RH1" at 231.028,0.508 h3 r90
  text "RH2" at 241.278,0.508 h3 r90
  text "RH7" at 251.273,0.508 h3 r90
  text "RH8" at 261.396,0.508 h3 r90
  text "DR7" at 271.518,0.508 h3 r90
  text "DR8" at 281.641,0.508 h3 r90
  text "DR5" at 302.013,0.508 h3 r90
  text "TO1" at 352.627,0.508 h3 r90
  text "TO2" at 362.936,0.508 h3 r90
  text "RH6" at 190.41,0.381 h3 r90
  text "RH5" at 200.787,0.381 h3 r90
  text "RH4" at 312.263,0.381 h3 r90
  text "RH3" at 322.259,0.381 h3 r90
  text "DR2" at 332.381,0.381 h3 r90
  text "DR1" at 342.504,0.381 h3 r90
  text "REC" at 373.253,0.381 h3 r90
